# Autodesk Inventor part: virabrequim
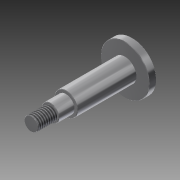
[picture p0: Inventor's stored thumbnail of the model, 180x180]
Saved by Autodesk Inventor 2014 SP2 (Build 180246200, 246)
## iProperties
Created: 2016-04
Part Number: virabrequim
Material: Genérico
Document SubType Name: Modeling
Designer: Celiberto
Density: 1 g/cm^3
Appearance: Prata
Mass: 3.73446 g
Surface Area: 20.8441 cm^2
Volume: 3.73446 cm^3
Author: Celiberto
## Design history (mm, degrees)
sketch "Esboço1"
  geometry: C1 r 3 at (0, 0); 1 further point
  constraints: 1 centre point, 1 coincident
  dimensions: "d0" = 6 diameter of C1
extrude "Extrusão1" new body sketch "Esboço1" distance "d1" = 8.2; taper "d2" = 0 deg
sketch "Esboço2"
  geometry: C1 r 3 at (0, 0) reference; C2 r 3.75 at (0, 0)
  constraints: 1 centre point, 1 coincident
  dimensions: "d3" = 7.5 diameter of C2
extrude "Extrusão2" join sketch "Esboço2" distance "d4" = 6.8; taper "d5" = 0 deg
sketch "Esboço3"
  geometry: C1 r 3.75 at (0, 0) reference; C2 r 5 at (0, 0)
  constraints: 1 centre point, 1 coincident
  dimensions: "d6" = 10 diameter of C2
extrude "Extrusão3" join sketch "Esboço3" distance "d7" = 25.5; taper "d8" = 0 deg
sketch "Esboço4"
  geometry: C1 r 5 at (0, 0) reference; C2 r 10.5 at (0, 0)
  constraints: 1 centre point, 1 coincident
  dimensions: "d9" = 21 diameter of C2
extrude "Extrusão4" join sketch "Esboço4" distance "d10" = 3.2; taper "d11" = 0 deg
sketch "Esboço5"
  geometry: C1 r 10.5 at (0, 0) reference; C2 r 2.4 at (0, 7.6)
  constraints: 1 centre point
  dimensions: "d12" = 4.8 diameter of C2; "d13" = 7.6 distance of C2.centre C1.centre
extrude "Extrusão5" join sketch "Esboço5" distance "d14" = 2.2; taper "d15" = 0 deg
sketch "Esboço6"
  geometry: C1 r 2.4 at (0, 0) reference; C2 r 1.9 at (0, 0); 1 further point
  constraints: 1 centre point, 1 coincident
  dimensions: "d16" = 3.8 diameter of C2
extrude "Extrusão6" join sketch "Esboço6" distance "d17" = 5; taper "d18" = 0 deg
chamfer "Chanfro1" distance "d19" = 0.2; stored, may be unused: second distance "d20" = 2, angle "d21" = 45 deg
chamfer "Chanfro2" distance "d22" = 0.5; stored, may be unused: second distance "d23" = 2, angle "d24" = 45 deg
feature "Rosca1" dims "d25" = 10, "d26" = 0
node "Sólido1"
